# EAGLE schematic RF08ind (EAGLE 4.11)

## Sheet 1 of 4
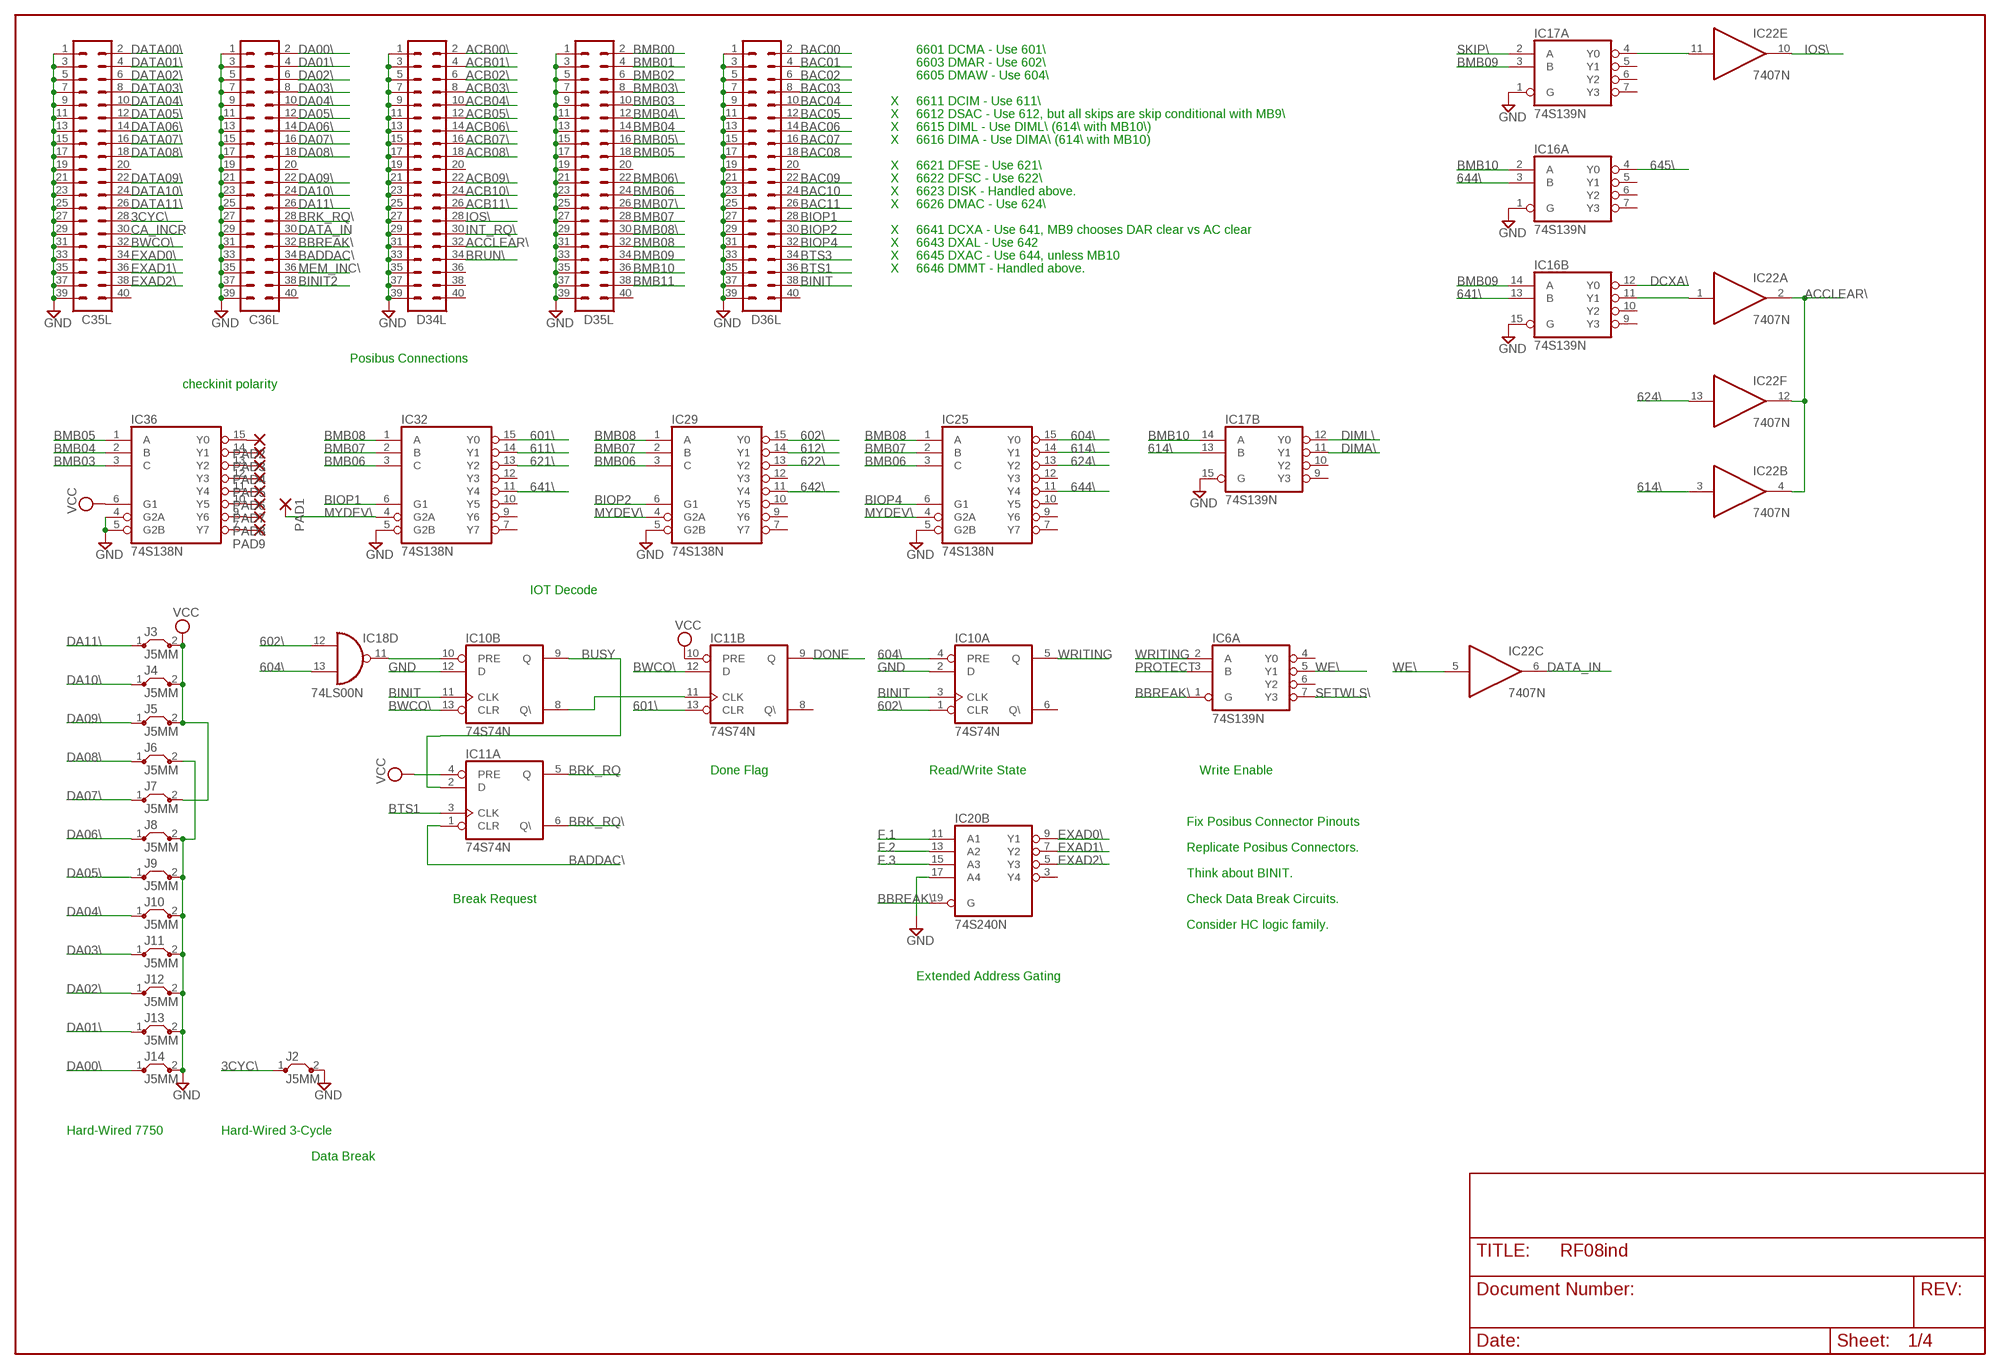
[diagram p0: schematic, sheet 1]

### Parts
C35L  MA20-2  [MA20-2]
C36L  MA20-2  [MA20-2]
D34L  MA20-2  [MA20-2]
D35L  MA20-2  [MA20-2]
D36L  MA20-2  [MA20-2]
IC6  74S139N  [DIL16]
IC10  74S74N  [DIL14]
IC11  74S74N  [DIL14]
IC16  74S139N  [DIL16]
IC17  74S139N  [DIL16]
IC18  74LS00N  [DIL14]
IC20  74S240N  [DIL20]
IC22  7407N  [DIL14]
IC25  74S138N  [DIL16]
IC29  74S138N  [DIL16]
IC32  74S138N  [DIL16]
IC36  74S138N  [DIL16]
J2  J5MM  [05]
J3  J5MM  [05]
J4  J5MM  [05]
J5  J5MM  [05]
J6  J5MM  [05]
J7  J5MM  [05]
J8  J5MM  [05]
J9  J5MM  [05]
J10  J5MM  [05]
J11  J5MM  [05]
J12  J5MM  [05]
J13  J5MM  [05]
J14  J5MM  [05]
PAD1  1,6/0,8  [1,6/0,8]
PAD2  1,6/0,8  [1,6/0,8]
PAD3  1,6/0,8  [1,6/0,8]
PAD4  1,6/0,8  [1,6/0,8]
PAD5  1,6/0,8  [1,6/0,8]
PAD6  1,6/0,8  [1,6/0,8]
PAD7  1,6/0,8  [1,6/0,8]
PAD8  1,6/0,8  [1,6/0,8]
PAD9  1,6/0,8  [1,6/0,8]

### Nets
3CYC\: C35L.28 J2.1
601\: IC11.13(B:CLR) IC32.15(Y0) ; also sheet 2
602\: IC10.1(A:CLR) IC18.12(D:I0) IC29.15(Y0) ; also sheet 2
604\: IC10.4(A:PRE) IC18.13(D:I1) IC25.15(Y0) ; also sheet 2
611\: IC32.14(Y1) ; also sheet 2
612\: IC29.14(Y1) ; also sheet 2
614\: IC17.13(B:B) IC22.3(B:I) IC25.14(Y1)
621\: IC32.13(Y2) ; also sheet 2
622\: IC29.13(Y2) ; also sheet 2
624\: IC22.13(F:I) IC25.13(Y2) ; also sheet 2
641\: IC16.13(B:B) IC32.11(Y4)
642\: IC29.11(Y4) ; also sheet 2
644\: IC16.3(A:B) IC25.11(Y4)
645\: IC16.4(A:Y0) ; also sheet 2
ACB00\: D34L.2 ; also sheet 2
ACB01\: D34L.4 ; also sheet 2
ACB02\: D34L.6 ; also sheet 2
ACB03\: D34L.8 ; also sheet 2
ACB04\: D34L.10 ; also sheet 2
ACB05\: D34L.12 ; also sheet 2
ACB06\: D34L.14 ; also sheet 2
ACB07\: D34L.16 ; also sheet 2
ACB08\: D34L.18 ; also sheet 2
ACB09\: D34L.22 ; also sheet 2
ACB10\: D34L.24 ; also sheet 2
ACB11\: D34L.26 ; also sheet 2
ACCLEAR\: D34L.32 IC22.2(A:O) IC22.4(B:O) IC22.12(F:O)
BAC00: D36L.2 ; also sheet 2
BAC01: D36L.4 ; also sheet 2
BAC02: D36L.6 ; also sheet 2
BAC03: D36L.8 ; also sheet 2
BAC04: D36L.10 ; also sheet 2
BAC05: D36L.12 ; also sheet 2
BAC06: D36L.14 ; also sheet 2
BAC07: D36L.16 ; also sheet 2
BAC08: D36L.18 ; also sheet 2
BAC09: D36L.22 ; also sheet 2
BAC10: D36L.24 ; also sheet 2
BAC11: D36L.26 ; also sheet 2
BADDAC\: C36L.34 IC11.1(A:CLR)
BBREAK\: C36L.32 IC6.1(A:G) IC20.19(B:G) ; also sheet 2,3
BINIT: D36L.38 IC10.3(A:CLK) IC10.11(B:CLK) ; also sheet 2
BINIT2: C36L.38
BIOP1: D36L.28 IC32.6(G1)
BIOP2: D36L.30 IC29.6(G1)
BIOP4: D36L.32 IC25.6(G1)
BMB00: D35L.2 ; also sheet 3
BMB01: D35L.4 ; also sheet 3
BMB02: D35L.6 ; also sheet 3
BMB03: D35L.10 IC36.3(C) ; also sheet 3
BMB03\: D35L.8
BMB04: D35L.14 IC36.2(B) ; also sheet 3
BMB04\: D35L.12
BMB05: D35L.18 IC36.1(A) ; also sheet 3
BMB05\: D35L.16
BMB06: D35L.24 IC25.3(C) IC29.3(C) IC32.3(C) ; also sheet 3
BMB06\: D35L.22
BMB07: D35L.28 IC25.2(B) IC29.2(B) IC32.2(B) ; also sheet 3
BMB07\: D35L.26
BMB08: D35L.32 IC25.1(A) IC29.1(A) IC32.1(A) ; also sheet 3
BMB08\: D35L.30
BMB09: D35L.34 IC16.14(B:A) IC17.3(A:B) ; also sheet 3
BMB10: D35L.36 IC16.2(A:A) IC17.14(B:A) ; also sheet 3
BMB11: D35L.38 ; also sheet 3
BRK_RQ: IC11.5(A:Q) ; also sheet 4
BRK_RQ\: C36L.28 IC11.6(A:Q\)
BRUN\: D34L.34
BTS1: D36L.36 IC11.3(A:CLK)
BTS3: D36L.34
BUSY: IC10.9(B:Q) IC11.2(A:D) ; also sheet 2
BWCO\: C35L.32 IC10.13(B:CLR) IC11.12(B:D) ; also sheet 4
CA_INCR: C35L.30
DA00\: C36L.2 J14.1
DA01\: C36L.4 J13.1
DA02\: C36L.6 J12.1
DA03\: C36L.8 J11.1
DA04\: C36L.10 J10.1
DA05\: C36L.12 J9.1
DA06\: C36L.14 J8.1
DA07\: C36L.16 J7.1
DA08\: C36L.18 J6.1
DA09\: C36L.22 J5.1
DA10\: C36L.24 J4.1
DA11\: C36L.26 J3.1
DATA00\: C35L.2 ; also sheet 3
DATA01\: C35L.4 ; also sheet 3
DATA02\: C35L.6 ; also sheet 3
DATA03\: C35L.8 ; also sheet 3
DATA04\: C35L.10 ; also sheet 3
DATA05\: C35L.12 ; also sheet 3
DATA06\: C35L.14 ; also sheet 3
DATA07\: C35L.16 ; also sheet 3
DATA08\: C35L.18 ; also sheet 3
DATA09\: C35L.22 ; also sheet 3
DATA10\: C35L.24 ; also sheet 3
DATA11\: C35L.26 ; also sheet 3
DATA_IN: C36L.30 IC22.6(C:O)
DCXA\: IC16.12(B:Y0) ; also sheet 2
DIMA\: IC17.11(B:Y1) ; also sheet 2
DIML\: IC17.12(B:Y0) ; also sheet 2
DONE: IC11.9(B:Q) ; also sheet 2,4
EXAD0\: C35L.34 IC20.9(B:Y1)
EXAD1\: C35L.36 IC20.7(B:Y2)
EXAD2\: C35L.38 IC20.5(B:Y3)
F.1: IC20.11(B:A1) ; also sheet 2,4
F.2: IC20.13(B:A2) ; also sheet 2,4
F.3: IC20.15(B:A3) ; also sheet 2,4
GND [Power]: C35L.1 C35L.3 C35L.5 C35L.7 C35L.9 C35L.11 C35L.13 C35L.15 C35L.17 C35L.19 C35L.21 C35L.23 C35L.25 C35L.27 C35L.29 C35L.31 C35L.33 C35L.35 C35L.37 C35L.39 C36L.1 C36L.3 C36L.5 C36L.7 C36L.9 C36L.11 C36L.13 C36L.15 C36L.17 C36L.19 C36L.21 C36L.23 C36L.25 C36L.27 C36L.29 C36L.31 C36L.33 C36L.35 C36L.37 C36L.39 D34L.1 D34L.3 D34L.5 D34L.7 D34L.9 D34L.11 D34L.13 D34L.15 D34L.17 D34L.19 D34L.21 D34L.23 D34L.25 D34L.27 D34L.29 D34L.31 D34L.33 D34L.35 D34L.37 D34L.39 D35L.1 D35L.3 D35L.5 D35L.7 D35L.9 D35L.11 D35L.13 D35L.15 D35L.17 D35L.19 D35L.21 D35L.23 D35L.25 D35L.27 D35L.29 D35L.31 D35L.33 D35L.35 D35L.37 D35L.39 D36L.1 D36L.3 D36L.5 D36L.7 D36L.9 D36L.11 D36L.13 D36L.15 D36L.17 D36L.19 D36L.21 D36L.23 D36L.25 D36L.27 D36L.29 D36L.31 D36L.33 D36L.35 D36L.37 D36L.39 IC10.2(A:D) IC10.12(B:D) IC16.1(A:G) IC16.15(B:G) IC17.1(A:G) IC17.15(B:G) IC20.17(B:A4) IC25.5(G2B) IC29.5(G2B) IC32.5(G2B) IC36.4(G2A) IC36.5(G2B) J2.2 J6.2 J8.2 J9.2 J10.2 J11.2 J12.2 J13.2 J14.2 ; also sheet 2,3
INT_RQ\: D34L.30 ; also sheet 2
IOS\: D34L.28 IC22.10(E:O)
MEM_INC\: C36L.36
MYDEV\: IC25.4(G2A) IC29.4(G2A) IC32.4(G2A) PAD1.1(P)
N$1: IC36.9(Y6) PAD8.1(P)
N$2: IC10.8(B:Q\) IC11.11(B:CLK)
N$5: IC36.15(Y0) PAD2.1(P)
N$6: IC36.14(Y1) PAD3.1(P)
N$7: IC36.13(Y2) PAD4.1(P)
N$8: IC36.12(Y3) PAD5.1(P)
N$9: IC36.11(Y4) PAD6.1(P)
N$10: IC36.10(Y5) PAD7.1(P)
N$11: IC36.7(Y7) PAD9.1(P)
N$26: IC16.11(B:Y1) IC22.1(A:I)
N$27: IC17.4(A:Y0) IC22.11(E:I)
N$31: IC10.10(B:PRE) IC18.11(D:O)
PROTECT: IC6.3(A:B) ; also sheet 3
SETWLS\: IC6.7(A:Y3) ; also sheet 2
SKIP\: IC17.2(A:A) ; also sheet 2
VCC [Power]: IC11.4(A:PRE) IC11.10(B:PRE) IC36.6(G1) J3.2 J4.2 J5.2 J7.2 ; also sheet 2,3,4
WE\: IC6.5(A:Y1) IC22.5(C:I) ; also sheet 3
WRITING: IC6.2(A:A) IC10.5(A:Q) ; also sheet 3,4
Unconnected: C35L.20 C35L.40 C36L.20 C36L.40 D34L.20 D34L.36 D34L.38 D34L.40 D35L.20 D35L.40 D36L.20 D36L.40 IC6.4(A:Y0) IC6.6(A:Y2) IC6.9(B:Y3) IC6.10(B:Y2) IC6.11(B:Y1) IC6.12(B:Y0) IC6.13(B:B) IC6.14(B:A) IC6.15(B:G) IC10.6(A:Q\) IC11.8(B:Q\) IC16.5(A:Y1) IC16.6(A:Y2) IC16.7(A:Y3) IC16.9(B:Y3) IC16.10(B:Y2) IC17.5(A:Y1) IC17.6(A:Y2) IC17.7(A:Y3) IC17.9(B:Y3) IC17.10(B:Y2) IC20.1(A:G) IC20.2(A:A1) IC20.3(B:Y4) IC20.4(A:A2) IC20.6(A:A3) IC20.8(A:A4) IC20.12(A:Y4) IC20.14(A:Y3) IC20.16(A:Y2) IC20.18(A:Y1) IC22.8(D:O) IC22.9(D:I) IC25.7(Y7) IC25.9(Y6) IC25.10(Y5) IC25.12(Y3) IC29.7(Y7) IC29.9(Y6) IC29.10(Y5) IC29.12(Y3) IC32.7(Y7) IC32.9(Y6) IC32.10(Y5) IC32.12(Y3)

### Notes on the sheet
- 6601 DCMA - Use 601\
- 6603 DMAR - Use 602\
- 6605 DMAW - Use 604\
- X | 6611 DCIM - Use 611\
- X | 6612 DSAC - Use 612\, but all skips are skip conditional with MB9\
- X | 6615 DIML - Use DIML\ (614\ with MB10\)
- X | 6616 DIMA - Use DIMA\ (614\ with MB10)
- X | 6621 DFSE - Use 621\
- X | 6622 DFSC - Use 622\
- X | 6623 DISK - Handled above.
- X | 6626 DMAC - Use 624\
- X | 6641 DCXA - Use 641, MB9 chooses DAR clear vs AC clear
- X | 6643 DXAL - Use 642
- X | 6645 DXAC - Use 644, unless MB10
- X | 6646 DMMT - Handled above.
- Posibus Connections
- checkinit polarity
- IOT Decode
- Done Flag | Read/Write State | Write Enable
- Fix Posibus Connector Pinouts
- Replicate Posibus Connectors.
- Think about BINIT.
- Break Request | Check Data Break Circuits.
- Consider HC logic family.
- Extended Address Gating
- Hard-Wired 7750 | Hard-Wired 3-Cycle
- Data Break

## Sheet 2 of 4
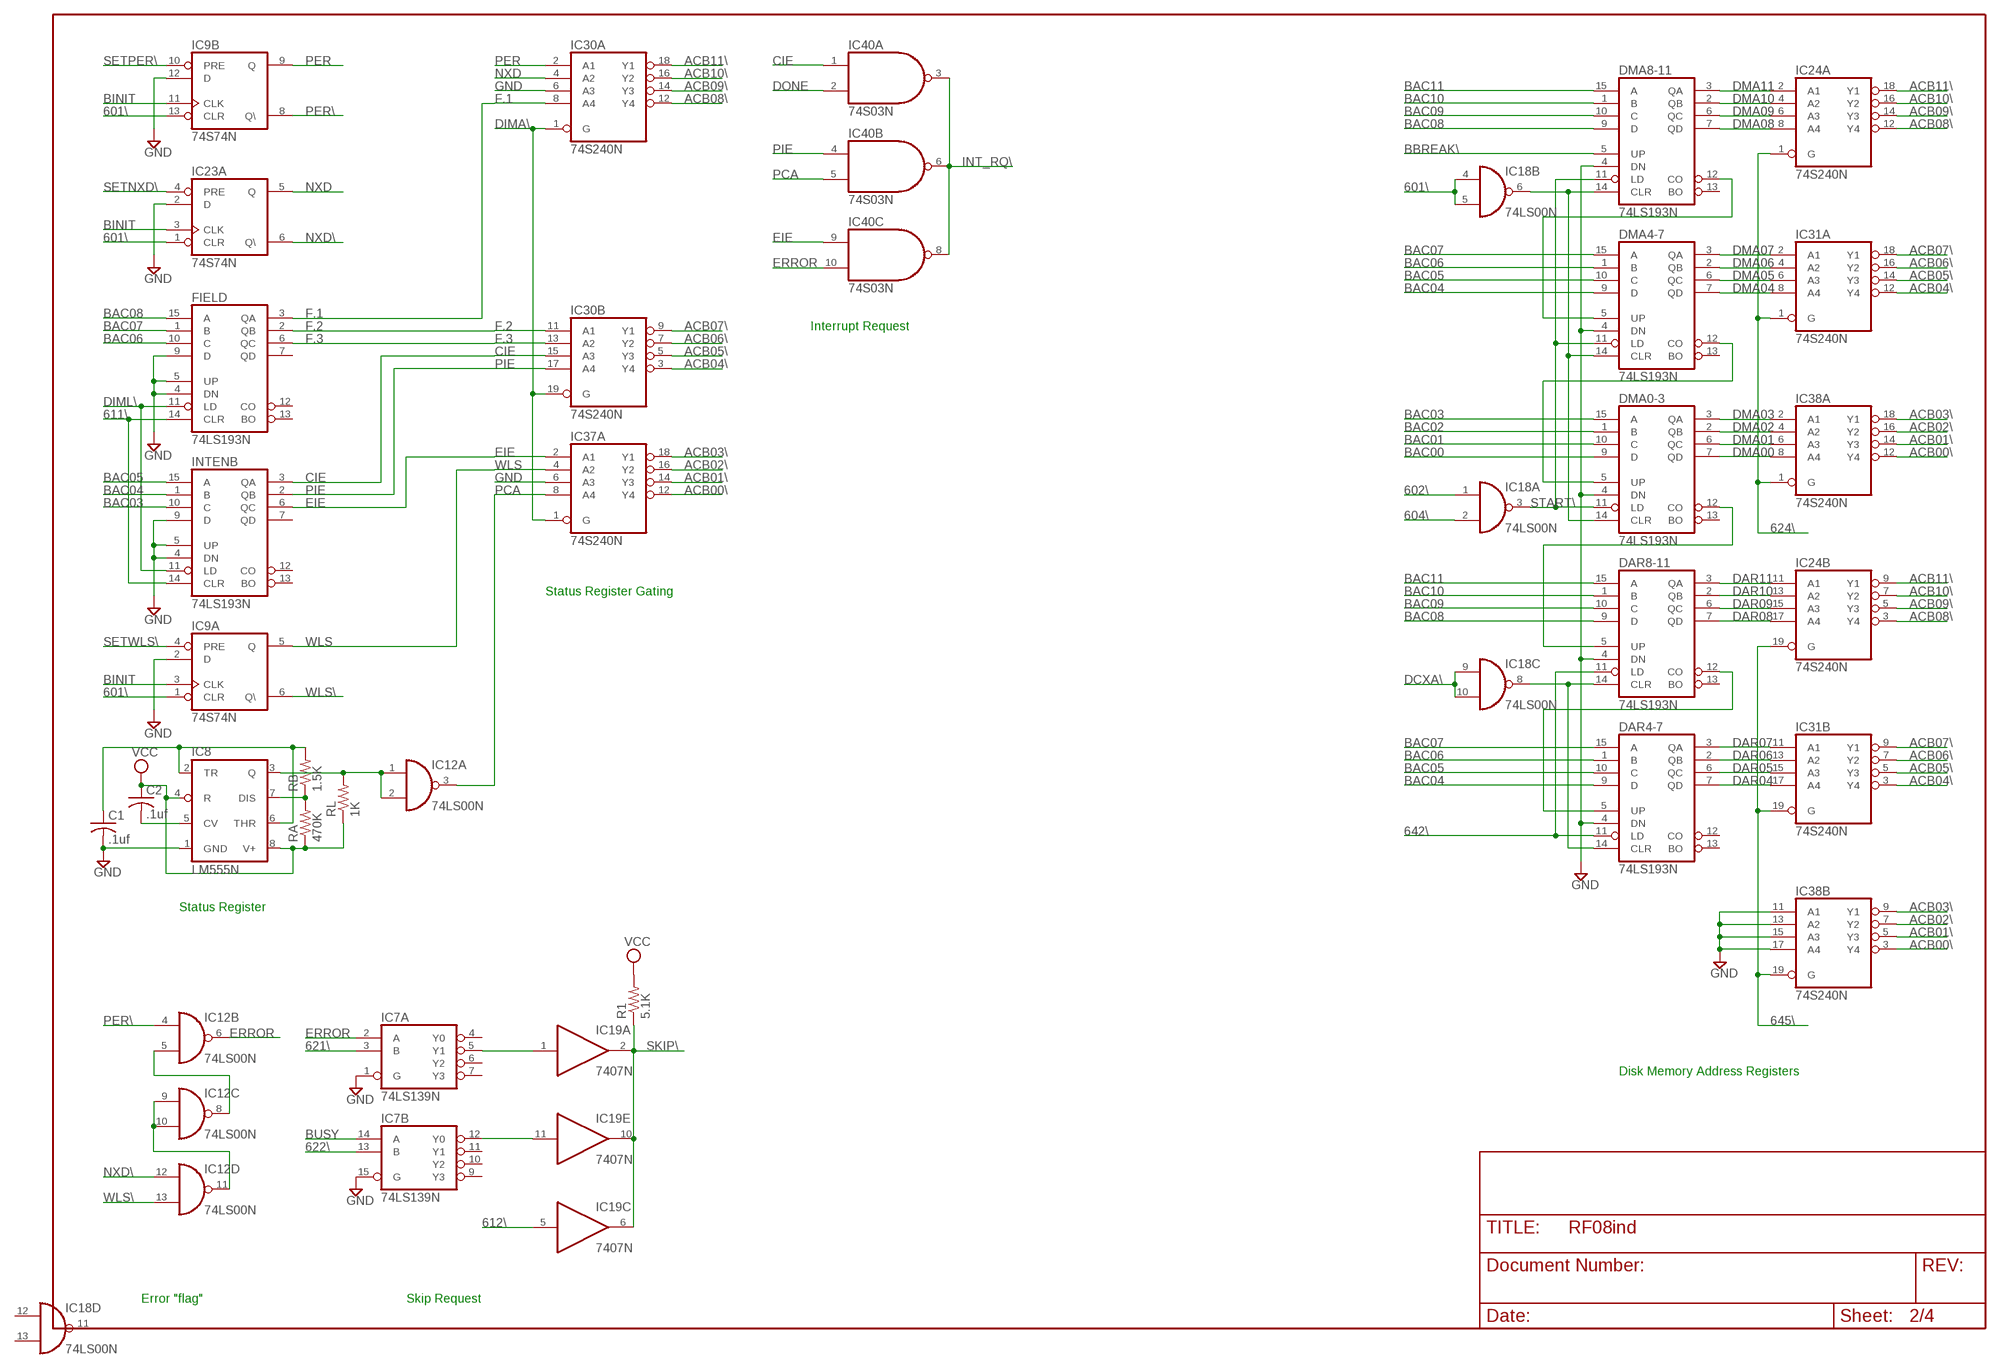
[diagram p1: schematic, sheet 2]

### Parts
C1  .1uf  C-US050-025X075  [C050-025X075]
C2  .1uf  C-US050-025X075  [C050-025X075]
DAR4-7  74LS193N  74LS192N  [DIL16]
DAR8-11  74LS193N  74LS192N  [DIL16]
DMA0-3  74LS193N  74LS192N  [DIL16]
DMA4-7  74LS193N  74LS192N  [DIL16]
DMA8-11  74LS193N  74LS192N  [DIL16]
FIELD  74LS193N  74LS192N  [DIL16]
IC7  74LS139N  [DIL16]
IC8  LM555N  [DIL08]
IC9  74S74N  [DIL14]
IC12  74LS00N  [DIL14]
IC19  7407N  [DIL14]
IC23  74S74N  [DIL14]
IC24  74S240N  [DIL20]
IC30  74S240N  [DIL20]
IC31  74S240N  [DIL20]
IC37  74S240N  [DIL20]
IC38  74S240N  [DIL20]
IC40  74S03N  [DIL14]
INTENB  74LS193N  74LS192N  [DIL16]
R1  5.1K  R-US_0207/10  [0207/10]
RA  470K  R-US_0207/10  [0207/10]
RB  1.5K  R-US_0207/10  [0207/10]
RL  1K  R-US_0207/10  [0207/10]

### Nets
601\: IC9.1(A:CLR) IC9.13(B:CLR) IC18.4(B:I0) IC18.5(B:I1) IC23.1(A:CLR) ; also sheet 1
602\: IC18.1(A:I0) ; also sheet 1
604\: IC18.2(A:I1) ; also sheet 1
611\: FIELD.14(CLR) INTENB.14(CLR) ; also sheet 1
612\: IC19.5(C:I) ; also sheet 1
621\: IC7.3(A:B) ; also sheet 1
622\: IC7.13(B:B) ; also sheet 1
624\: IC24.1(A:G) IC31.1(A:G) IC38.1(A:G) ; also sheet 1
642\: DAR4-7.11(LD) DAR8-11.11(LD) ; also sheet 1
645\: IC24.19(B:G) IC31.19(B:G) IC38.19(B:G) ; also sheet 1
ACB00\: IC37.12(A:Y4) IC38.3(B:Y4) IC38.12(A:Y4) ; also sheet 1
ACB01\: IC37.14(A:Y3) IC38.5(B:Y3) IC38.14(A:Y3) ; also sheet 1
ACB02\: IC37.16(A:Y2) IC38.7(B:Y2) IC38.16(A:Y2) ; also sheet 1
ACB03\: IC37.18(A:Y1) IC38.9(B:Y1) IC38.18(A:Y1) ; also sheet 1
ACB04\: IC30.3(B:Y4) IC31.3(B:Y4) IC31.12(A:Y4) ; also sheet 1
ACB05\: IC30.5(B:Y3) IC31.5(B:Y3) IC31.14(A:Y3) ; also sheet 1
ACB06\: IC30.7(B:Y2) IC31.7(B:Y2) IC31.16(A:Y2) ; also sheet 1
ACB07\: IC30.9(B:Y1) IC31.9(B:Y1) IC31.18(A:Y1) ; also sheet 1
ACB08\: IC24.3(B:Y4) IC24.12(A:Y4) IC30.12(A:Y4) ; also sheet 1
ACB09\: IC24.5(B:Y3) IC24.14(A:Y3) IC30.14(A:Y3) ; also sheet 1
ACB10\: IC24.7(B:Y2) IC24.16(A:Y2) IC30.16(A:Y2) ; also sheet 1
ACB11\: IC24.9(B:Y1) IC24.18(A:Y1) IC30.18(A:Y1) ; also sheet 1
BAC00: DMA0-3.9(D) ; also sheet 1
BAC01: DMA0-3.10(C) ; also sheet 1
BAC02: DMA0-3.1(B) ; also sheet 1
BAC03: DMA0-3.15(A) INTENB.10(C) ; also sheet 1
BAC04: DAR4-7.9(D) DMA4-7.9(D) INTENB.1(B) ; also sheet 1
BAC05: DAR4-7.10(C) DMA4-7.10(C) INTENB.15(A) ; also sheet 1
BAC06: DAR4-7.1(B) DMA4-7.1(B) FIELD.10(C) ; also sheet 1
BAC07: DAR4-7.15(A) DMA4-7.15(A) FIELD.1(B) ; also sheet 1
BAC08: DAR8-11.9(D) DMA8-11.9(D) FIELD.15(A) ; also sheet 1
BAC09: DAR8-11.10(C) DMA8-11.10(C) ; also sheet 1
BAC10: DAR8-11.1(B) DMA8-11.1(B) ; also sheet 1
BAC11: DAR8-11.15(A) DMA8-11.15(A) ; also sheet 1
BBREAK\: DMA8-11.5(UP) ; also sheet 1,3
BINIT: IC9.3(A:CLK) IC9.11(B:CLK) IC23.3(A:CLK) ; also sheet 1
BUSY: IC7.14(B:A) ; also sheet 1
CIE: IC30.15(B:A3) IC40.1(A:I0) INTENB.3(QA) ; also sheet 4
DAR04: DAR4-7.7(QD) IC31.17(B:A4) ; also sheet 3,4
DAR05: DAR4-7.6(QC) IC31.15(B:A3) ; also sheet 3,4
DAR06: DAR4-7.2(QB) IC31.13(B:A2) ; also sheet 3,4
DAR07: DAR4-7.3(QA) IC31.11(B:A1) ; also sheet 3,4
DAR08: DAR8-11.7(QD) IC24.17(B:A4) ; also sheet 3,4
DAR09: DAR8-11.6(QC) IC24.15(B:A3) ; also sheet 3,4
DAR10: DAR8-11.2(QB) IC24.13(B:A2) ; also sheet 3,4
DAR11: DAR8-11.3(QA) IC24.11(B:A1) ; also sheet 3,4
DCXA\: IC18.9(C:I0) IC18.10(C:I1) ; also sheet 1
DIMA\: IC30.1(A:G) IC30.19(B:G) IC37.1(A:G) ; also sheet 1
DIML\: FIELD.11(LD) INTENB.11(LD) ; also sheet 1
DMA00: DMA0-3.7(QD) IC38.8(A:A4) ; also sheet 3,4
DMA01: DMA0-3.6(QC) IC38.6(A:A3) ; also sheet 3,4
DMA02: DMA0-3.2(QB) IC38.4(A:A2) ; also sheet 3,4
DMA03: DMA0-3.3(QA) IC38.2(A:A1) ; also sheet 3,4
DMA04: DMA4-7.7(QD) IC31.8(A:A4) ; also sheet 3,4
DMA05: DMA4-7.6(QC) IC31.6(A:A3) ; also sheet 3,4
DMA06: DMA4-7.2(QB) IC31.4(A:A2) ; also sheet 3,4
DMA07: DMA4-7.3(QA) IC31.2(A:A1) ; also sheet 3,4
DMA08: DMA8-11.7(QD) IC24.8(A:A4) ; also sheet 3,4
DMA09: DMA8-11.6(QC) IC24.6(A:A3) ; also sheet 3,4
DMA10: DMA8-11.2(QB) IC24.4(A:A2) ; also sheet 3,4
DMA11: DMA8-11.3(QA) IC24.2(A:A1) ; also sheet 3,4
DONE: IC40.2(A:I1) ; also sheet 1,4
EIE: IC37.2(A:A1) IC40.9(C:I0) INTENB.6(QC) ; also sheet 4
ERROR: IC7.2(A:A) IC12.6(B:O) IC40.10(C:I1)
F.1: FIELD.3(QA) IC30.8(A:A4) ; also sheet 1,4
F.2: FIELD.2(QB) IC30.11(B:A1) ; also sheet 1,4
F.3: FIELD.6(QC) IC30.13(B:A2) ; also sheet 1,4
GND [Power]: C1.2 DAR4-7.4(DN) DAR8-11.4(DN) DMA0-3.4(DN) DMA4-7.4(DN) DMA8-11.4(DN) FIELD.4(DN) FIELD.5(UP) FIELD.9(D) IC7.1(A:G) IC7.15(B:G) IC8.1(GND) IC9.2(A:D) IC9.12(B:D) IC23.2(A:D) IC30.6(A:A3) IC37.6(A:A3) IC38.11(B:A1) IC38.13(B:A2) IC38.15(B:A3) IC38.17(B:A4) INTENB.4(DN) INTENB.5(UP) INTENB.9(D) ; also sheet 1,3
INT_RQ\: IC40.3(A:O) IC40.6(B:O) IC40.8(C:O) ; also sheet 1
N$3: DMA0-3.5(UP) DMA4-7.12(CO)
N$12: DAR4-7.14(CLR) DAR8-11.14(CLR) IC18.8(C:O)
N$13: DMA4-7.5(UP) DMA8-11.12(CO)
N$16: DAR8-11.5(UP) DMA0-3.12(CO)
N$22: DMA0-3.14(CLR) DMA4-7.14(CLR) DMA8-11.14(CLR) IC18.6(B:O)
N$25: DAR4-7.5(UP) DAR8-11.12(CO)
N$28: IC7.5(A:Y1) IC19.1(A:I)
N$29: IC8.7(DIS) RA.2 RB.1
N$30: IC8.3(Q) IC12.1(A:I0) IC12.2(A:I1) RL.2
N$32: C1.1 IC8.2(TR) IC8.6(THR) RB.2
N$33: IC7.12(B:Y0) IC19.11(E:I)
N$34: C2.2 IC8.5(CV)
N$37: IC12.9(C:I0) IC12.10(C:I1) IC12.11(D:O)
N$40: IC12.5(B:I1) IC12.8(C:O)
NXD: IC23.5(A:Q) IC30.4(A:A2) ; also sheet 4
NXD\: IC12.12(D:I0) IC23.6(A:Q\)
PCA: IC12.3(A:O) IC37.8(A:A4) IC40.5(B:I1)
PER: IC9.9(B:Q) IC30.2(A:A1) ; also sheet 4
PER\: IC9.8(B:Q\) IC12.4(B:I0)
PIE: IC30.17(B:A4) IC40.4(B:I0) INTENB.2(QB) ; also sheet 4
SETNXD\: IC23.4(A:PRE) ; also sheet 3
SETPER\: IC9.10(B:PRE) ; also sheet 3
SETWLS\: IC9.4(A:PRE) ; also sheet 1
SKIP\: IC19.2(A:O) IC19.6(C:O) IC19.10(E:O) R1.1 ; also sheet 1
START\: DMA0-3.11(LD) DMA4-7.11(LD) DMA8-11.11(LD) IC18.3(A:O)
VCC [Power]: C2.1 IC8.4(R) IC8.8(V+) R1.2 RA.1 RL.1 ; also sheet 1,3,4
WLS: IC9.5(A:Q) IC37.4(A:A2) ; also sheet 4
WLS\: IC9.6(A:Q\) IC12.13(D:I1)
Unconnected: DAR4-7.12(CO) DAR4-7.13(BO) DAR8-11.13(BO) DMA0-3.13(BO) DMA4-7.13(BO) DMA8-11.13(BO) FIELD.7(QD) FIELD.12(CO) FIELD.13(BO) IC7.4(A:Y0) IC7.6(A:Y2) IC7.7(A:Y3) IC7.9(B:Y3) IC7.10(B:Y2) IC7.11(B:Y1) IC19.3(B:I) IC19.4(B:O) IC19.8(D:O) IC19.9(D:I) IC19.12(F:O) IC19.13(F:I) IC23.8(B:Q\) IC23.9(B:Q) IC23.10(B:PRE) IC23.11(B:CLK) IC23.12(B:D) IC23.13(B:CLR) IC37.3(B:Y4) IC37.5(B:Y3) IC37.7(B:Y2) IC37.9(B:Y1) IC37.11(B:A1) IC37.13(B:A2) IC37.15(B:A3) IC37.17(B:A4) IC37.19(B:G) IC40.11(D:O) IC40.12(D:I0) IC40.13(D:I1) INTENB.7(QD) INTENB.12(CO) INTENB.13(BO)

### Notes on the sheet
- Interrupt Request
- Status Register Gating
- Status Register
- Disk Memory Address Registers
- Error "flag" | Skip Request

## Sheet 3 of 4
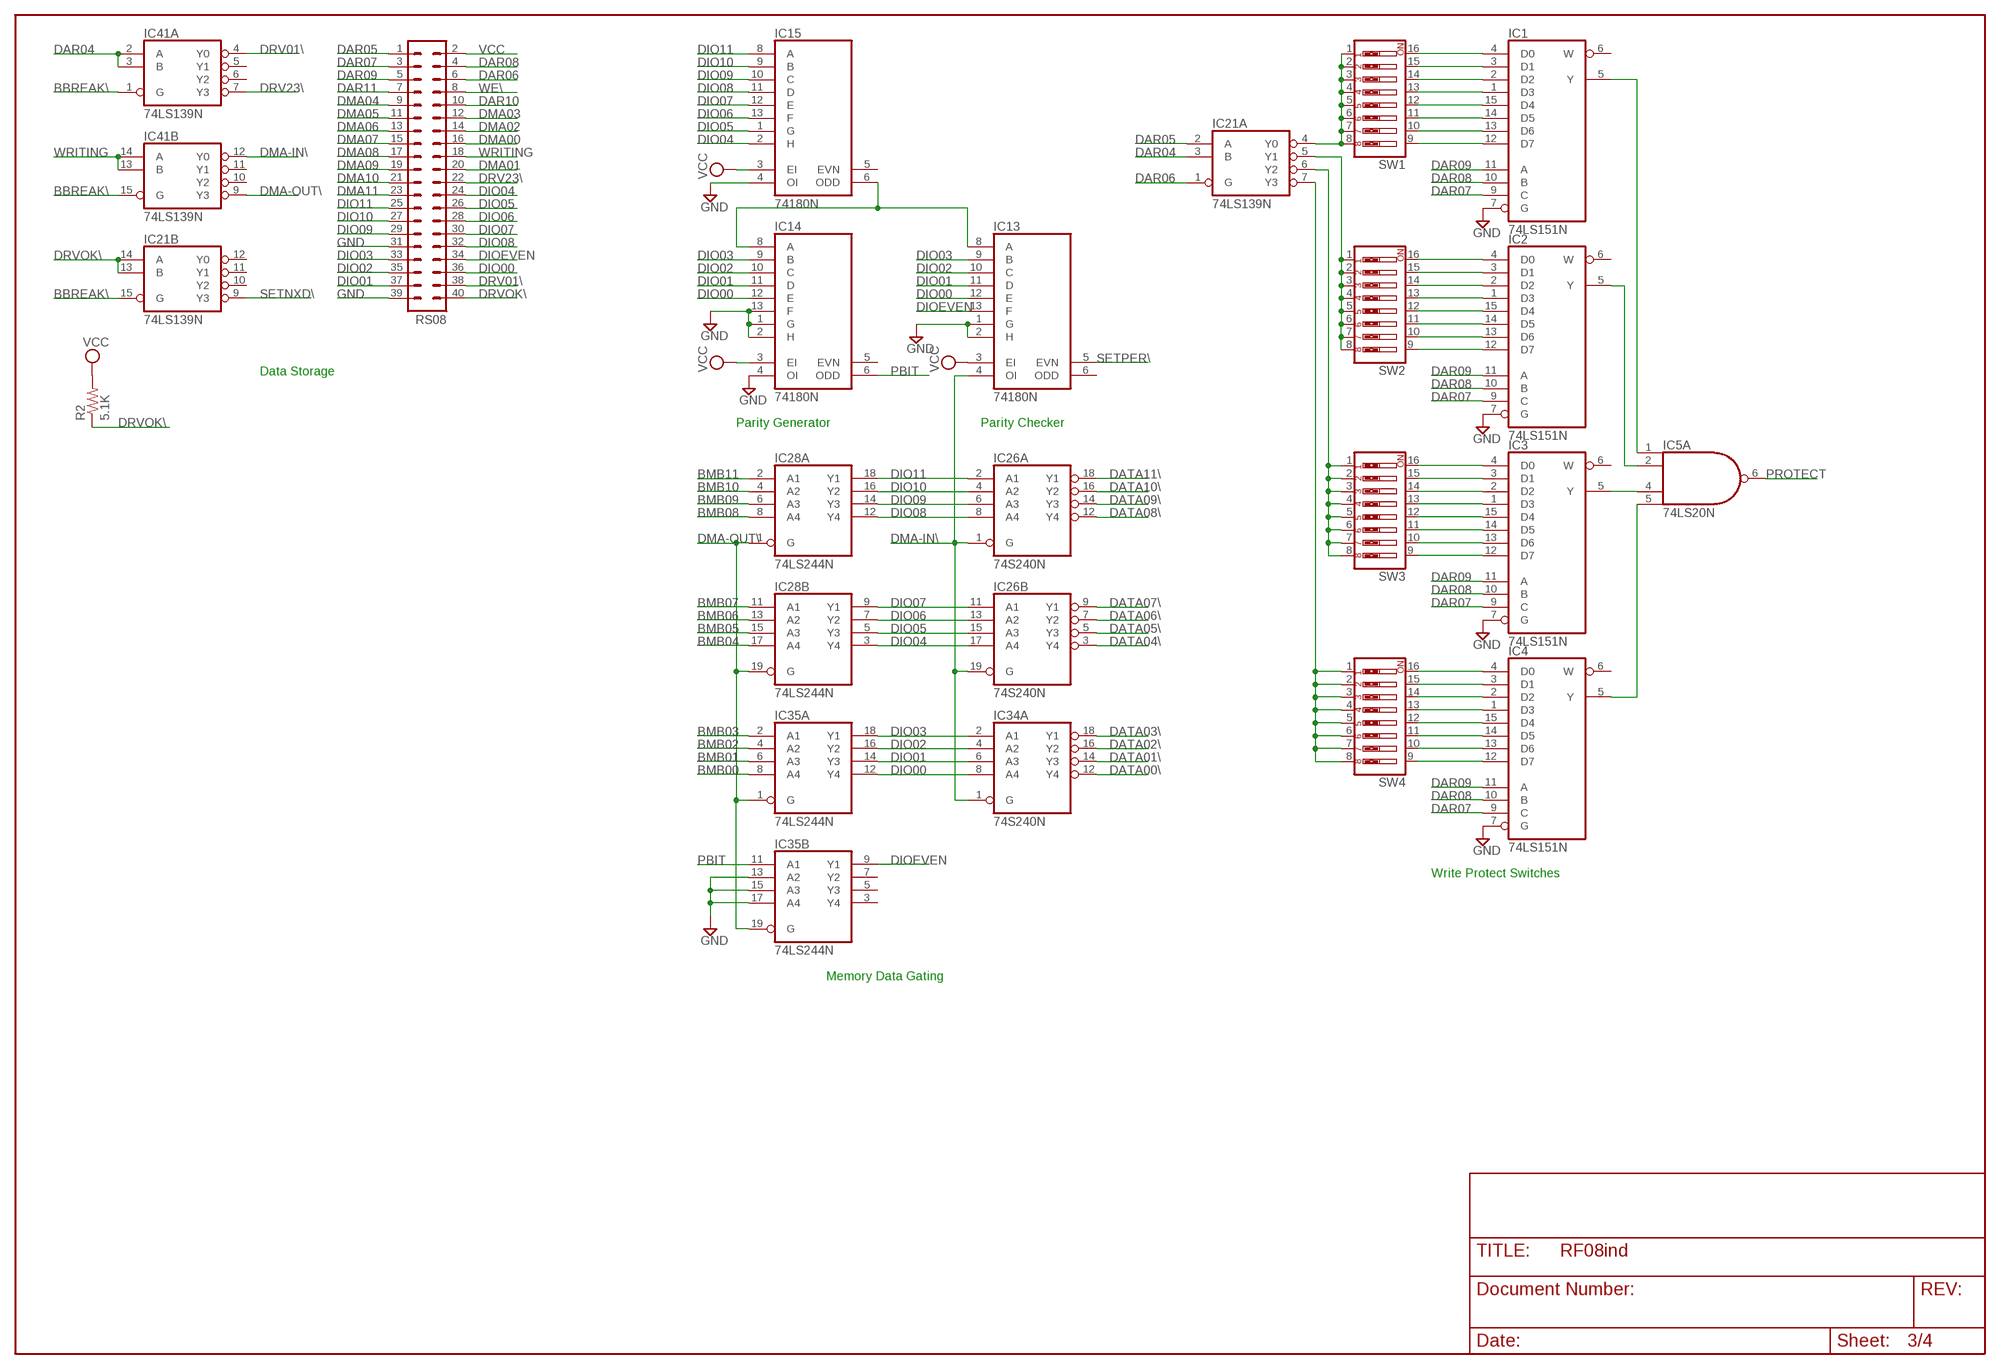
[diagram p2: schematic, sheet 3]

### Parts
IC1  74LS151N  [DIL16]
IC2  74LS151N  [DIL16]
IC3  74LS151N  [DIL16]
IC4  74LS151N  [DIL16]
IC5  74LS20N  [DIL14]
IC13  74180N  [DIL14]
IC14  74180N  [DIL14]
IC15  74180N  [DIL14]
IC21  74LS139N  [DIL16]
IC26  74S240N  [DIL20]
IC28  74LS244N  [DIL20]
IC34  74S240N  [DIL20]
IC35  74LS244N  [DIL20]
IC41  74LS139N  [DIL16]
R2  5.1K  R-US_0207/10  [0207/10]
RS08  MA20-2  [MA20-2]
SW1  SW_DIP-8  [EDG-08]
SW2  SW_DIP-8  [EDG-08]
SW3  SW_DIP-8  [EDG-08]
SW4  SW_DIP-8  [EDG-08]

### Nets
BBREAK\: IC21.15(B:G) IC41.1(A:G) IC41.15(B:G) ; also sheet 1,2
BMB00: IC35.8(A:A4) ; also sheet 1
BMB01: IC35.6(A:A3) ; also sheet 1
BMB02: IC35.4(A:A2) ; also sheet 1
BMB03: IC35.2(A:A1) ; also sheet 1
BMB04: IC28.17(B:A4) ; also sheet 1
BMB05: IC28.15(B:A3) ; also sheet 1
BMB06: IC28.13(B:A2) ; also sheet 1
BMB07: IC28.11(B:A1) ; also sheet 1
BMB08: IC28.8(A:A4) ; also sheet 1
BMB09: IC28.6(A:A3) ; also sheet 1
BMB10: IC28.4(A:A2) ; also sheet 1
BMB11: IC28.2(A:A1) ; also sheet 1
DAR04: IC21.3(A:B) IC41.2(A:A) IC41.3(A:B) ; also sheet 2,4
DAR05: IC21.2(A:A) RS08.1 ; also sheet 2,4
DAR06: IC21.1(A:G) RS08.6 ; also sheet 2,4
DAR07: IC1.9(C) IC2.9(C) IC3.9(C) IC4.9(C) RS08.3 ; also sheet 2,4
DAR08: IC1.10(B) IC2.10(B) IC3.10(B) IC4.10(B) RS08.4 ; also sheet 2,4
DAR09: IC1.11(A) IC2.11(A) IC3.11(A) IC4.11(A) RS08.5 ; also sheet 2,4
DAR10: RS08.10 ; also sheet 2,4
DAR11: RS08.7 ; also sheet 2,4
DATA00\: IC34.12(A:Y4) ; also sheet 1
DATA01\: IC34.14(A:Y3) ; also sheet 1
DATA02\: IC34.16(A:Y2) ; also sheet 1
DATA03\: IC34.18(A:Y1) ; also sheet 1
DATA04\: IC26.3(B:Y4) ; also sheet 1
DATA05\: IC26.5(B:Y3) ; also sheet 1
DATA06\: IC26.7(B:Y2) ; also sheet 1
DATA07\: IC26.9(B:Y1) ; also sheet 1
DATA08\: IC26.12(A:Y4) ; also sheet 1
DATA09\: IC26.14(A:Y3) ; also sheet 1
DATA10\: IC26.16(A:Y2) ; also sheet 1
DATA11\: IC26.18(A:Y1) ; also sheet 1
DIO00: IC13.12(E) IC14.12(E) IC34.8(A:A4) IC35.12(A:Y4) RS08.36 ; also sheet 4
DIO01: IC13.11(D) IC14.11(D) IC34.6(A:A3) IC35.14(A:Y3) RS08.37 ; also sheet 4
DIO02: IC13.10(C) IC14.10(C) IC34.4(A:A2) IC35.16(A:Y2) RS08.35 ; also sheet 4
DIO03: IC13.9(B) IC14.9(B) IC34.2(A:A1) IC35.18(A:Y1) RS08.33 ; also sheet 4
DIO04: IC15.2(H) IC26.17(B:A4) IC28.3(B:Y4) RS08.24 ; also sheet 4
DIO05: IC15.1(G) IC26.15(B:A3) IC28.5(B:Y3) RS08.26 ; also sheet 4
DIO06: IC15.13(F) IC26.13(B:A2) IC28.7(B:Y2) RS08.28 ; also sheet 4
DIO07: IC15.12(E) IC26.11(B:A1) IC28.9(B:Y1) RS08.30 ; also sheet 4
DIO08: IC15.11(D) IC26.8(A:A4) IC28.12(A:Y4) RS08.32 ; also sheet 4
DIO09: IC15.10(C) IC26.6(A:A3) IC28.14(A:Y3) RS08.29 ; also sheet 4
DIO10: IC15.9(B) IC26.4(A:A2) IC28.16(A:Y2) RS08.27 ; also sheet 4
DIO11: IC15.8(A) IC26.2(A:A1) IC28.18(A:Y1) RS08.25 ; also sheet 4
DIOEVEN: IC13.13(F) IC35.9(B:Y1) RS08.34
DMA00: RS08.16 ; also sheet 2,4
DMA01: RS08.20 ; also sheet 2,4
DMA02: RS08.14 ; also sheet 2,4
DMA03: RS08.12 ; also sheet 2,4
DMA04: RS08.9 ; also sheet 2,4
DMA05: RS08.11 ; also sheet 2,4
DMA06: RS08.13 ; also sheet 2,4
DMA07: RS08.15 ; also sheet 2,4
DMA08: RS08.17 ; also sheet 2,4
DMA09: RS08.19 ; also sheet 2,4
DMA10: RS08.21 ; also sheet 2,4
DMA11: RS08.23 ; also sheet 2,4
DMA-IN\: IC13.4(OI) IC26.1(A:G) IC26.19(B:G) IC34.1(A:G) IC41.12(B:Y0)
DMA-OUT\: IC28.1(A:G) IC28.19(B:G) IC35.1(A:G) IC35.19(B:G) IC41.9(B:Y3)
DRV01\: IC41.4(A:Y0) RS08.38
DRV23\: IC41.7(A:Y3) RS08.22
DRVOK\: IC21.13(B:B) IC21.14(B:A) R2.1 RS08.40
GND [Power]: IC1.7(G) IC2.7(G) IC3.7(G) IC4.7(G) IC13.1(G) IC13.2(H) IC14.1(G) IC14.2(H) IC14.4(OI) IC14.13(F) IC15.4(OI) IC35.13(B:A2) IC35.15(B:A3) IC35.17(B:A4) RS08.31 RS08.39 ; also sheet 1,2
N$4: IC21.4(A:Y0) SW1.1 SW1.2 SW1.3 SW1.4 SW1.5 SW1.6 SW1.7 SW1.8
N$14: IC13.8(A) IC14.8(A) IC15.6(ODD)
N$15: IC2.5(Y) IC5.2(A:I1)
N$17: IC21.5(A:Y1) SW2.1 SW2.2 SW2.3 SW2.4 SW2.5 SW2.6 SW2.7 SW2.8
N$19: IC21.6(A:Y2) SW3.1 SW3.2 SW3.3 SW3.4 SW3.5 SW3.6 SW3.7 SW3.8
N$20: IC21.7(A:Y3) SW4.1 SW4.2 SW4.3 SW4.4 SW4.5 SW4.6 SW4.7 SW4.8
N$21: IC3.5(Y) IC5.4(A:I2)
N$23: IC1.5(Y) IC5.1(A:I0)
N$24: IC4.5(Y) IC5.5(A:I3)
N$53: IC1.4(D0) SW1.16
N$54: IC1.3(D1) SW1.15
N$55: IC1.2(D2) SW1.14
N$56: IC1.1(D3) SW1.13
N$57: IC1.14(D5) SW1.11
N$58: IC1.13(D6) SW1.10
N$59: IC1.12(D7) SW1.9
N$60: IC1.15(D4) SW1.12
N$61: IC2.4(D0) SW2.16
N$62: IC2.3(D1) SW2.15
N$63: IC2.2(D2) SW2.14
N$64: IC2.1(D3) SW2.13
N$65: IC2.14(D5) SW2.11
N$66: IC2.13(D6) SW2.10
N$67: IC2.12(D7) SW2.9
N$68: IC3.4(D0) SW3.16
N$69: IC3.3(D1) SW3.15
N$70: IC3.2(D2) SW3.14
N$71: IC3.1(D3) SW3.13
N$72: IC3.14(D5) SW3.11
N$73: IC3.13(D6) SW3.10
N$74: IC3.12(D7) SW3.9
N$75: IC4.4(D0) SW4.16
N$76: IC4.3(D1) SW4.15
N$77: IC4.2(D2) SW4.14
N$78: IC4.1(D3) SW4.13
N$79: IC4.14(D5) SW4.11
N$80: IC4.13(D6) SW4.10
N$81: IC4.12(D7) SW4.9
N$82: IC4.15(D4) SW4.12
N$83: IC3.15(D4) SW3.12
N$84: IC2.15(D4) SW2.12
PBIT: IC14.6(ODD) IC35.11(B:A1)
PROTECT: IC5.6(A:O) ; also sheet 1
SETNXD\: IC21.9(B:Y3) ; also sheet 2
SETPER\: IC13.5(EVN) ; also sheet 2
VCC [Power]: IC13.3(EI) IC14.3(EI) IC15.3(EI) R2.2 RS08.2 ; also sheet 1,2,4
WE\: RS08.8 ; also sheet 1
WRITING: IC41.13(B:B) IC41.14(B:A) RS08.18 ; also sheet 1,4
Unconnected: IC1.6(W) IC2.6(W) IC3.6(W) IC4.6(W) IC5.8(B:O) IC5.9(B:I0) IC5.10(B:I1) IC5.12(B:I2) IC5.13(B:I3) IC13.6(ODD) IC14.5(EVN) IC15.5(EVN) IC21.10(B:Y2) IC21.11(B:Y1) IC21.12(B:Y0) IC34.3(B:Y4) IC34.5(B:Y3) IC34.7(B:Y2) IC34.9(B:Y1) IC34.11(B:A1) IC34.13(B:A2) IC34.15(B:A3) IC34.17(B:A4) IC34.19(B:G) IC35.3(B:Y4) IC35.5(B:Y3) IC35.7(B:Y2) IC41.5(A:Y1) IC41.6(A:Y2) IC41.10(B:Y2) IC41.11(B:Y1)

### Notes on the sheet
- Data Storage
- Parity Generator | Parity Checker
- Write Protect Switches
- Memory Data Gating

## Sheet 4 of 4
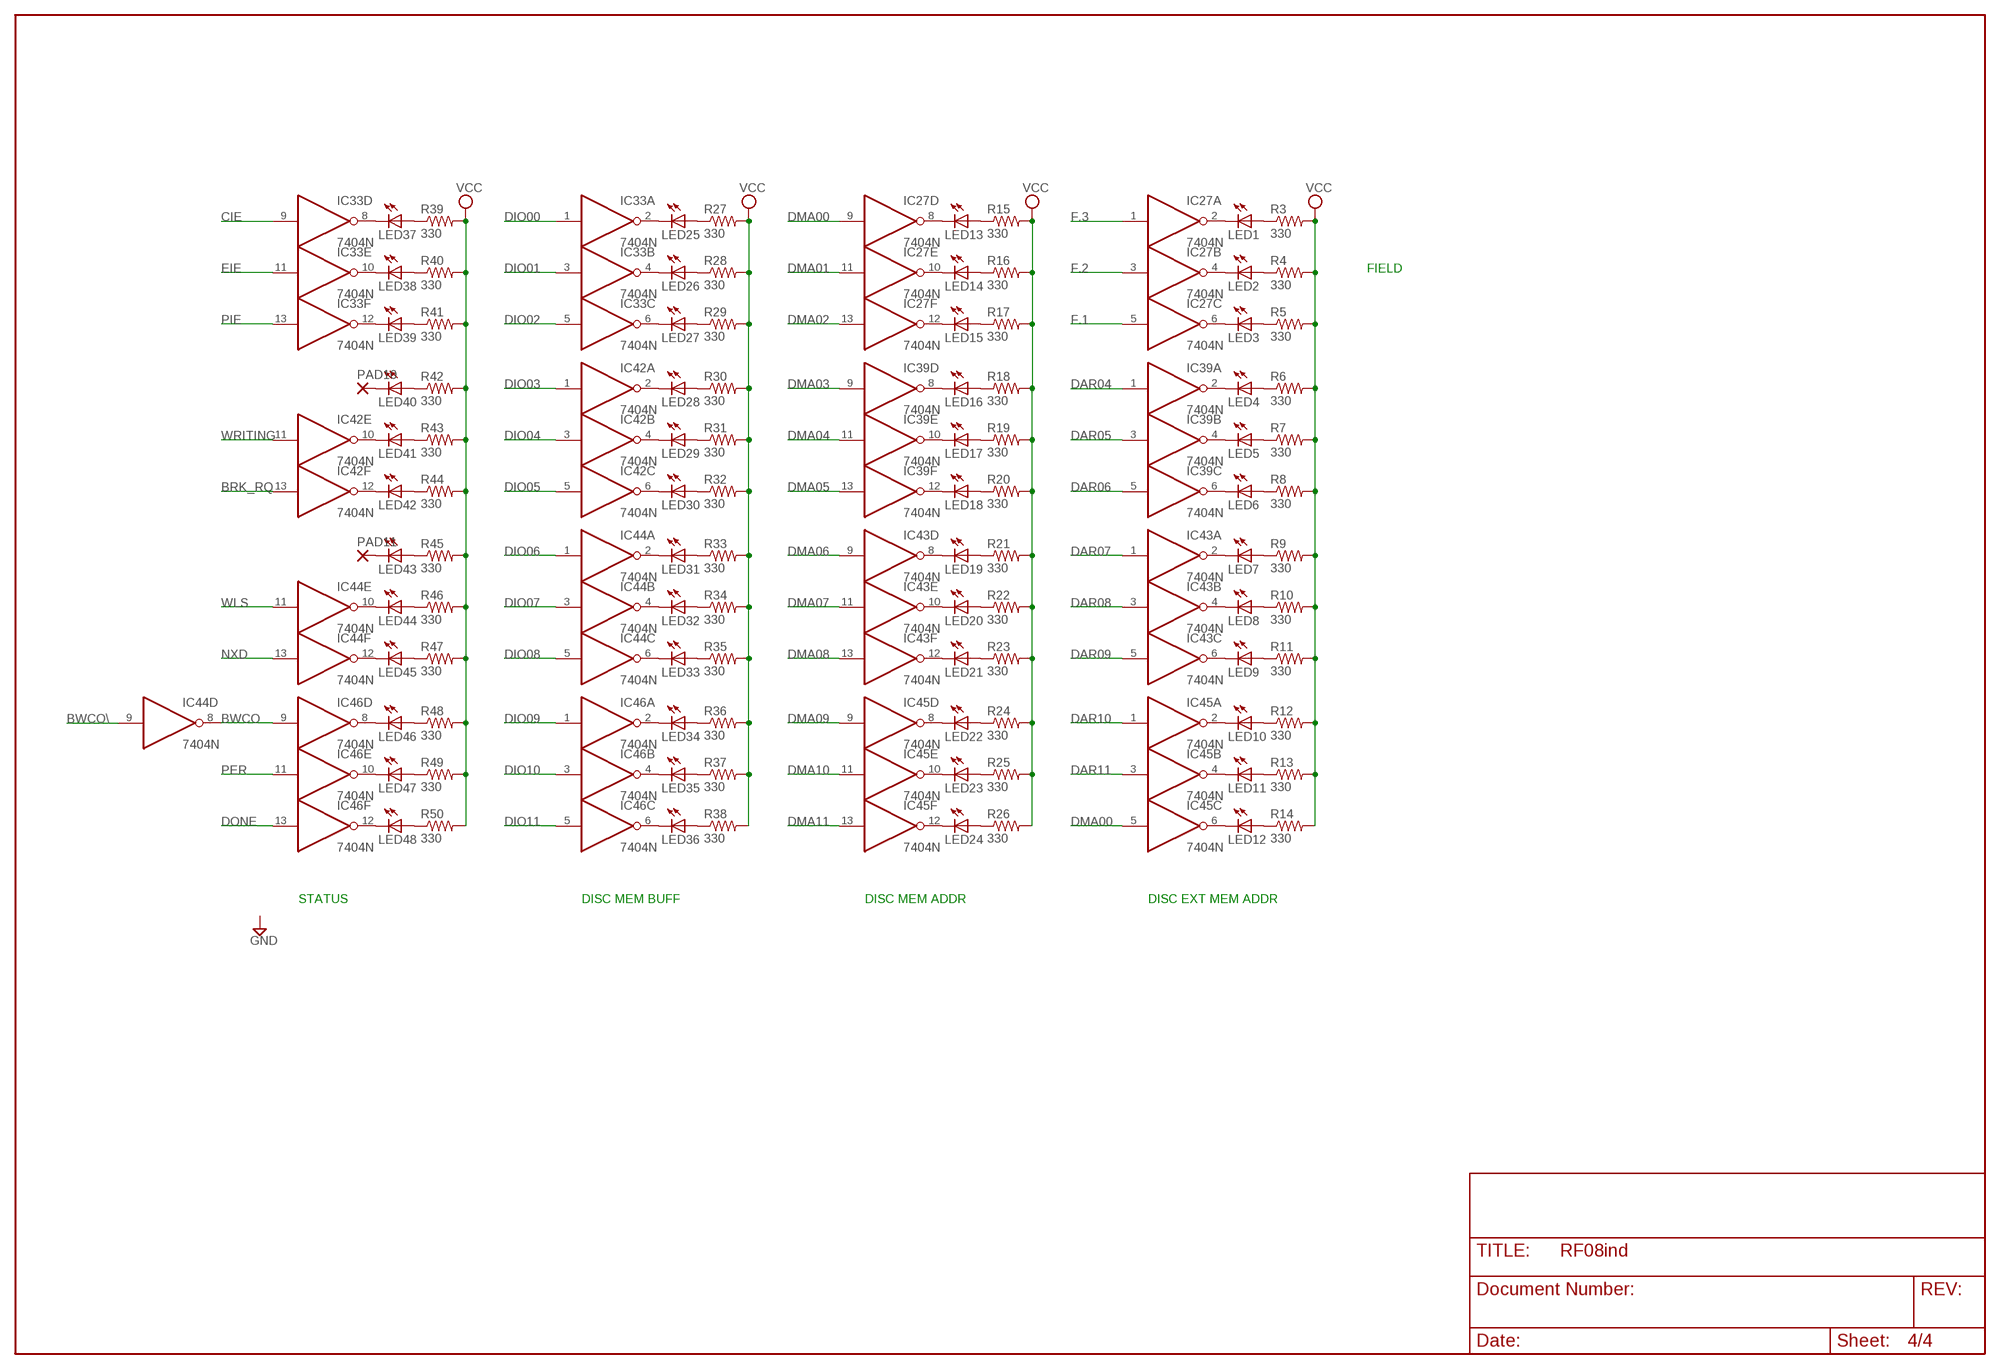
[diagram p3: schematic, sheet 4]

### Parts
IC27  7404N  [DIL14]
IC33  7404N  [DIL14]
IC39  7404N  [DIL14]
IC42  7404N  [DIL14]
IC43  7404N  [DIL14]
IC44  7404N  [DIL14]
IC45  7404N  [DIL14]
IC46  7404N  [DIL14]
LED1  LED5MM  [LED5MM]
LED2  LED5MM  [LED5MM]
LED3  LED5MM  [LED5MM]
LED4  LED5MM  [LED5MM]
LED5  LED5MM  [LED5MM]
LED6  LED5MM  [LED5MM]
LED7  LED5MM  [LED5MM]
LED8  LED5MM  [LED5MM]
LED9  LED5MM  [LED5MM]
LED10  LED5MM  [LED5MM]
LED11  LED5MM  [LED5MM]
LED12  LED5MM  [LED5MM]
LED13  LED5MM  [LED5MM]
LED14  LED5MM  [LED5MM]
LED15  LED5MM  [LED5MM]
LED16  LED5MM  [LED5MM]
LED17  LED5MM  [LED5MM]
LED18  LED5MM  [LED5MM]
LED19  LED5MM  [LED5MM]
LED20  LED5MM  [LED5MM]
LED21  LED5MM  [LED5MM]
LED22  LED5MM  [LED5MM]
LED23  LED5MM  [LED5MM]
LED24  LED5MM  [LED5MM]
LED25  LED5MM  [LED5MM]
LED26  LED5MM  [LED5MM]
LED27  LED5MM  [LED5MM]
LED28  LED5MM  [LED5MM]
LED29  LED5MM  [LED5MM]
LED30  LED5MM  [LED5MM]
LED31  LED5MM  [LED5MM]
LED32  LED5MM  [LED5MM]
LED33  LED5MM  [LED5MM]
LED34  LED5MM  [LED5MM]
LED35  LED5MM  [LED5MM]
LED36  LED5MM  [LED5MM]
LED37  LED5MM  [LED5MM]
LED38  LED5MM  [LED5MM]
LED39  LED5MM  [LED5MM]
LED40  LED5MM  [LED5MM]
LED41  LED5MM  [LED5MM]
LED42  LED5MM  [LED5MM]
LED43  LED5MM  [LED5MM]
LED44  LED5MM  [LED5MM]
LED45  LED5MM  [LED5MM]
LED46  LED5MM  [LED5MM]
LED47  LED5MM  [LED5MM]
LED48  LED5MM  [LED5MM]
PAD10  1,6/0,8  [1,6/0,8]
PAD11  1,6/0,8  [1,6/0,8]
R3  330  R-US_0207/10  [0207/10]
R4  330  R-US_0207/10  [0207/10]
R5  330  R-US_0207/10  [0207/10]
R6  330  R-US_0207/10  [0207/10]
R7  330  R-US_0207/10  [0207/10]
R8  330  R-US_0207/10  [0207/10]
R9  330  R-US_0207/10  [0207/10]
R10  330  R-US_0207/10  [0207/10]
R11  330  R-US_0207/10  [0207/10]
R12  330  R-US_0207/10  [0207/10]
R13  330  R-US_0207/10  [0207/10]
R14  330  R-US_0207/10  [0207/10]
R15  330  R-US_0207/10  [0207/10]
R16  330  R-US_0207/10  [0207/10]
R17  330  R-US_0207/10  [0207/10]
R18  330  R-US_0207/10  [0207/10]
R19  330  R-US_0207/10  [0207/10]
R20  330  R-US_0207/10  [0207/10]
R21  330  R-US_0207/10  [0207/10]
R22  330  R-US_0207/10  [0207/10]
R23  330  R-US_0207/10  [0207/10]
R24  330  R-US_0207/10  [0207/10]
R25  330  R-US_0207/10  [0207/10]
R26  330  R-US_0207/10  [0207/10]
R27  330  R-US_0207/10  [0207/10]
R28  330  R-US_0207/10  [0207/10]
R29  330  R-US_0207/10  [0207/10]
R30  330  R-US_0207/10  [0207/10]
R31  330  R-US_0207/10  [0207/10]
R32  330  R-US_0207/10  [0207/10]
R33  330  R-US_0207/10  [0207/10]
R34  330  R-US_0207/10  [0207/10]
R35  330  R-US_0207/10  [0207/10]
R36  330  R-US_0207/10  [0207/10]
R37  330  R-US_0207/10  [0207/10]
R38  330  R-US_0207/10  [0207/10]
R39  330  R-US_0207/10  [0207/10]
R40  330  R-US_0207/10  [0207/10]
R41  330  R-US_0207/10  [0207/10]
R42  330  R-US_0207/10  [0207/10]
R43  330  R-US_0207/10  [0207/10]
R44  330  R-US_0207/10  [0207/10]
R45  330  R-US_0207/10  [0207/10]
R46  330  R-US_0207/10  [0207/10]
R47  330  R-US_0207/10  [0207/10]
R48  330  R-US_0207/10  [0207/10]
R49  330  R-US_0207/10  [0207/10]
R50  330  R-US_0207/10  [0207/10]

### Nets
BRK_RQ: IC42.13(F:I) ; also sheet 1
BWCO: IC44.8(D:O) IC46.9(D:I)
BWCO\: IC44.9(D:I) ; also sheet 1
CIE: IC33.9(D:I) ; also sheet 2
DAR04: IC39.1(A:I) ; also sheet 2,3
DAR05: IC39.3(B:I) ; also sheet 2,3
DAR06: IC39.5(C:I) ; also sheet 2,3
DAR07: IC43.1(A:I) ; also sheet 2,3
DAR08: IC43.3(B:I) ; also sheet 2,3
DAR09: IC43.5(C:I) ; also sheet 2,3
DAR10: IC45.1(A:I) ; also sheet 2,3
DAR11: IC45.3(B:I) ; also sheet 2,3
DIO00: IC33.1(A:I) ; also sheet 3
DIO01: IC33.3(B:I) ; also sheet 3
DIO02: IC33.5(C:I) ; also sheet 3
DIO03: IC42.1(A:I) ; also sheet 3
DIO04: IC42.3(B:I) ; also sheet 3
DIO05: IC42.5(C:I) ; also sheet 3
DIO06: IC44.1(A:I) ; also sheet 3
DIO07: IC44.3(B:I) ; also sheet 3
DIO08: IC44.5(C:I) ; also sheet 3
DIO09: IC46.1(A:I) ; also sheet 3
DIO10: IC46.3(B:I) ; also sheet 3
DIO11: IC46.5(C:I) ; also sheet 3
DMA00: IC27.9(D:I) IC45.5(C:I) ; also sheet 2,3
DMA01: IC27.11(E:I) ; also sheet 2,3
DMA02: IC27.13(F:I) ; also sheet 2,3
DMA03: IC39.9(D:I) ; also sheet 2,3
DMA04: IC39.11(E:I) ; also sheet 2,3
DMA05: IC39.13(F:I) ; also sheet 2,3
DMA06: IC43.9(D:I) ; also sheet 2,3
DMA07: IC43.11(E:I) ; also sheet 2,3
DMA08: IC43.13(F:I) ; also sheet 2,3
DMA09: IC45.9(D:I) ; also sheet 2,3
DMA10: IC45.11(E:I) ; also sheet 2,3
DMA11: IC45.13(F:I) ; also sheet 2,3
DONE: IC46.13(F:I) ; also sheet 1,2
EIE: IC33.11(E:I) ; also sheet 2
F.1: IC27.5(C:I) ; also sheet 1,2
F.2: IC27.3(B:I) ; also sheet 1,2
F.3: IC27.1(A:I) ; also sheet 1,2
N$18: LED1.A R3.1
N$35: LED2.A R4.1
N$36: LED3.A R5.1
N$38: LED4.A R6.1
N$39: LED5.A R7.1
N$41: LED6.A R8.1
N$42: LED7.A R9.1
N$43: LED8.A R10.1
N$44: LED9.A R11.1
N$45: LED10.A R12.1
N$46: LED11.A R13.1
N$47: LED12.A R14.1
N$48: LED13.A R15.1
N$49: LED14.A R16.1
N$50: LED15.A R17.1
N$51: LED16.A R18.1
N$52: LED17.A R19.1
N$85: LED18.A R20.1
N$86: LED19.A R21.1
N$87: LED20.A R22.1
N$88: LED21.A R23.1
N$89: LED22.A R24.1
N$90: LED23.A R25.1
N$91: LED24.A R26.1
N$92: LED25.A R27.1
N$93: LED26.A R28.1
N$94: LED27.A R29.1
N$95: LED28.A R30.1
N$96: LED29.A R31.1
N$97: LED30.A R32.1
N$98: LED31.A R33.1
N$99: LED32.A R34.1
N$100: LED33.A R35.1
N$101: LED34.A R36.1
N$102: LED35.A R37.1
N$103: LED36.A R38.1
N$104: LED37.A R39.1
N$105: LED38.A R40.1
N$106: LED39.A R41.1
N$107: LED40.A R42.1
N$108: LED41.A R43.1
N$109: LED42.A R44.1
N$110: LED43.A R45.1
N$111: LED44.A R46.1
N$112: LED45.A R47.1
N$113: LED46.A R48.1
N$114: LED47.A R49.1
N$115: LED48.A R50.1
N$116: LED40.K(C) PAD10.1(P)
N$117: IC27.2(A:O) LED1.K(C)
N$118: IC27.4(B:O) LED2.K(C)
N$119: IC27.6(C:O) LED3.K(C)
N$120: IC27.8(D:O) LED13.K(C)
N$121: IC27.10(E:O) LED14.K(C)
N$122: IC27.12(F:O) LED15.K(C)
N$123: IC33.2(A:O) LED25.K(C)
N$124: IC33.4(B:O) LED26.K(C)
N$125: IC33.6(C:O) LED27.K(C)
N$126: IC33.8(D:O) LED37.K(C)
N$127: IC33.10(E:O) LED38.K(C)
N$128: IC33.12(F:O) LED39.K(C)
N$129: LED43.K(C) PAD11.1(P)
N$130: IC39.4(B:O) LED5.K(C)
N$131: IC39.6(C:O) LED6.K(C)
N$132: IC39.8(D:O) LED16.K(C)
N$133: IC39.10(E:O) LED17.K(C)
N$134: IC39.12(F:O) LED18.K(C)
N$135: IC42.2(A:O) LED28.K(C)
N$136: IC42.4(B:O) LED29.K(C)
N$137: IC42.6(C:O) LED30.K(C)
N$138: IC39.2(A:O) LED4.K(C)
N$139: IC42.10(E:O) LED41.K(C)
N$140: IC42.12(F:O) LED42.K(C)
N$141: IC43.2(A:O) LED7.K(C)
N$142: IC43.4(B:O) LED8.K(C)
N$143: IC43.6(C:O) LED9.K(C)
N$144: IC43.8(D:O) LED19.K(C)
N$145: IC43.10(E:O) LED20.K(C)
N$146: IC43.12(F:O) LED21.K(C)
N$147: IC44.2(A:O) LED31.K(C)
N$148: IC44.4(B:O) LED32.K(C)
N$149: IC44.6(C:O) LED33.K(C)
N$151: IC44.10(E:O) LED44.K(C)
N$152: IC44.12(F:O) LED45.K(C)
N$153: IC45.2(A:O) LED10.K(C)
N$154: IC45.4(B:O) LED11.K(C)
N$155: IC45.6(C:O) LED12.K(C)
N$156: IC45.8(D:O) LED22.K(C)
N$157: IC45.10(E:O) LED23.K(C)
N$158: IC45.12(F:O) LED24.K(C)
N$159: IC46.2(A:O) LED34.K(C)
N$160: IC46.4(B:O) LED35.K(C)
N$161: IC46.6(C:O) LED36.K(C)
N$162: IC46.8(D:O) LED46.K(C)
N$163: IC46.10(E:O) LED47.K(C)
N$164: IC46.12(F:O) LED48.K(C)
NXD: IC44.13(F:I) ; also sheet 2
PER: IC46.11(E:I) ; also sheet 2
PIE: IC33.13(F:I) ; also sheet 2
VCC [Power]: R3.2 R4.2 R5.2 R6.2 R7.2 R8.2 R9.2 R10.2 R11.2 R12.2 R13.2 R14.2 R15.2 R16.2 R17.2 R18.2 R19.2 R20.2 R21.2 R22.2 R23.2 R24.2 R25.2 R26.2 R27.2 R28.2 R29.2 R30.2 R31.2 R32.2 R33.2 R34.2 R35.2 R36.2 R37.2 R38.2 R39.2 R40.2 R41.2 R42.2 R43.2 R44.2 R45.2 R46.2 R47.2 R48.2 R49.2 R50.2 ; also sheet 1,2,3
WLS: IC44.11(E:I) ; also sheet 2
WRITING: IC42.11(E:I) ; also sheet 1,3
Unconnected: IC42.8(D:O) IC42.9(D:I)

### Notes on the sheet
- FIELD
- STATUS | DISC MEM BUFF | DISC MEM ADDR | DISC EXT MEM ADDR

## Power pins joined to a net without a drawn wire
GND: DAR4-7.8(GND) DAR8-11.8(GND) DMA0-3.8(GND) DMA4-7.8(GND) DMA8-11.8(GND) FIELD.8(GND) IC1.8(GND) IC2.8(GND) IC3.8(GND) IC4.8(GND) IC5.7(P:GND) IC6.8(P:GND) IC7.8(P:GND) IC9.7(P:GND) IC10.7(P:GND) IC11.7(P:GND) IC12.7(P:GND) IC13.7(GND) IC14.7(GND) IC15.7(GND) IC16.8(P:GND) IC17.8(P:GND) IC18.7(P:GND) IC19.7(P:GND) IC20.10(P:GND) IC21.8(P:GND) IC22.7(P:GND) IC23.7(P:GND) IC24.10(P:GND) IC25.8(GND) IC26.10(P:GND) IC27.7(P:GND) IC28.10(P:GND) IC29.8(GND) IC30.10(P:GND) IC31.10(P:GND) IC32.8(GND) IC33.7(P:GND) IC34.10(P:GND) IC35.10(P:GND) IC36.8(GND) IC37.10(P:GND) IC38.10(P:GND) IC39.7(P:GND) IC40.7(P:GND) IC41.8(P:GND) IC42.7(P:GND) IC43.7(P:GND) IC44.7(P:GND) IC45.7(P:GND) IC46.7(P:GND) INTENB.8(GND)
VCC: DAR4-7.16(VCC) DAR8-11.16(VCC) DMA0-3.16(VCC) DMA4-7.16(VCC) DMA8-11.16(VCC) FIELD.16(VCC) IC1.16(VCC) IC2.16(VCC) IC3.16(VCC) IC4.16(VCC) IC5.14(P:VCC) IC6.16(P:VCC) IC7.16(P:VCC) IC9.14(P:VCC) IC10.14(P:VCC) IC11.14(P:VCC) IC12.14(P:VCC) IC13.14(VCC) IC14.14(VCC) IC15.14(VCC) IC16.16(P:VCC) IC17.16(P:VCC) IC18.14(P:VCC) IC19.14(P:VCC) IC20.20(P:VCC) IC21.16(P:VCC) IC22.14(P:VCC) IC23.14(P:VCC) IC24.20(P:VCC) IC25.16(VCC) IC26.20(P:VCC) IC27.14(P:VCC) IC28.20(P:VCC) IC29.16(VCC) IC30.20(P:VCC) IC31.20(P:VCC) IC32.16(VCC) IC33.14(P:VCC) IC34.20(P:VCC) IC35.20(P:VCC) IC36.16(VCC) IC37.20(P:VCC) IC38.20(P:VCC) IC39.14(P:VCC) IC40.14(P:VCC) IC41.16(P:VCC) IC42.14(P:VCC) IC43.14(P:VCC) IC44.14(P:VCC) IC45.14(P:VCC) IC46.14(P:VCC) INTENB.16(VCC)

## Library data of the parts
C1 C2 = rcl:C-US: CAPACITOR, American symbol
C35L C36L D34L D35L D36L RS08 = con-lstb:MA20-2: PIN HEADER
DAR4-7 DAR8-11 DMA0-3 DMA4-7 DMA8-11 FIELD INTENB = 74xx-us:74*192: Synchronous 4-bit UP/DOWN COUNTER
IC1-IC4 = 74xx-eu:74*151: Data SELECTOR/MULTIPLEXER
IC5 = 74xx-us:74*20: Dual 4-input NAND gate
IC6 IC7 IC16 IC17 IC21 IC41 = 74xx-us:74*139: Dual 2-line to 4-line DECODER/DEMULTIPLEXER
IC8 = linear:*555: TIMER
IC9-IC11 IC23 = 74xx-us:74*74: Dual D type positive edge triggered FLIP FLOP, preset and clear
IC12 IC18 = 74xx-eu:74*00: Quad 2-input NAND gate
IC13-IC15 = 74xx-us:74*180: 9-bit odd/even PARITY GENERATOR/CHECKER
IC19 IC22 = 74xx-us:74*07: Hex BUFFER, open collector high-voltage output
IC20 IC24 IC26 IC30 IC31 IC34 IC37 IC38 = 74xx-us:74*240: Octal BUFFER and LINE DRIVER, 3-state
IC25 IC29 IC32 IC36 = 74xx-us:74*138: 3-line to 8-line DECODER/DEMULTIPLEXER
IC27 IC33 IC39 IC42-IC46 = 74xx-us:74*04: Hex INVERTER
IC28 IC35 = 74xx-us:74*244: Octal BUFFER and LINE DRIVER, 3-state
IC40 = 74xx-us:74*03: Quad 2-input NAND gate, open collector output
J2-J14 = jumper:J: Bridge
LED1-LED48 = led:LED: LED
PAD1-PAD11 = wirepad:1,6/0,8: THROUGH-HOLE PAD
R1-R50 RA RB RL = rcl:R-US_: RESISTOR, American symbol
SW1-SW4 = special:SW_DIP-8: DIP SWITCH

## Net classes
1 Power: width 0.508 mm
